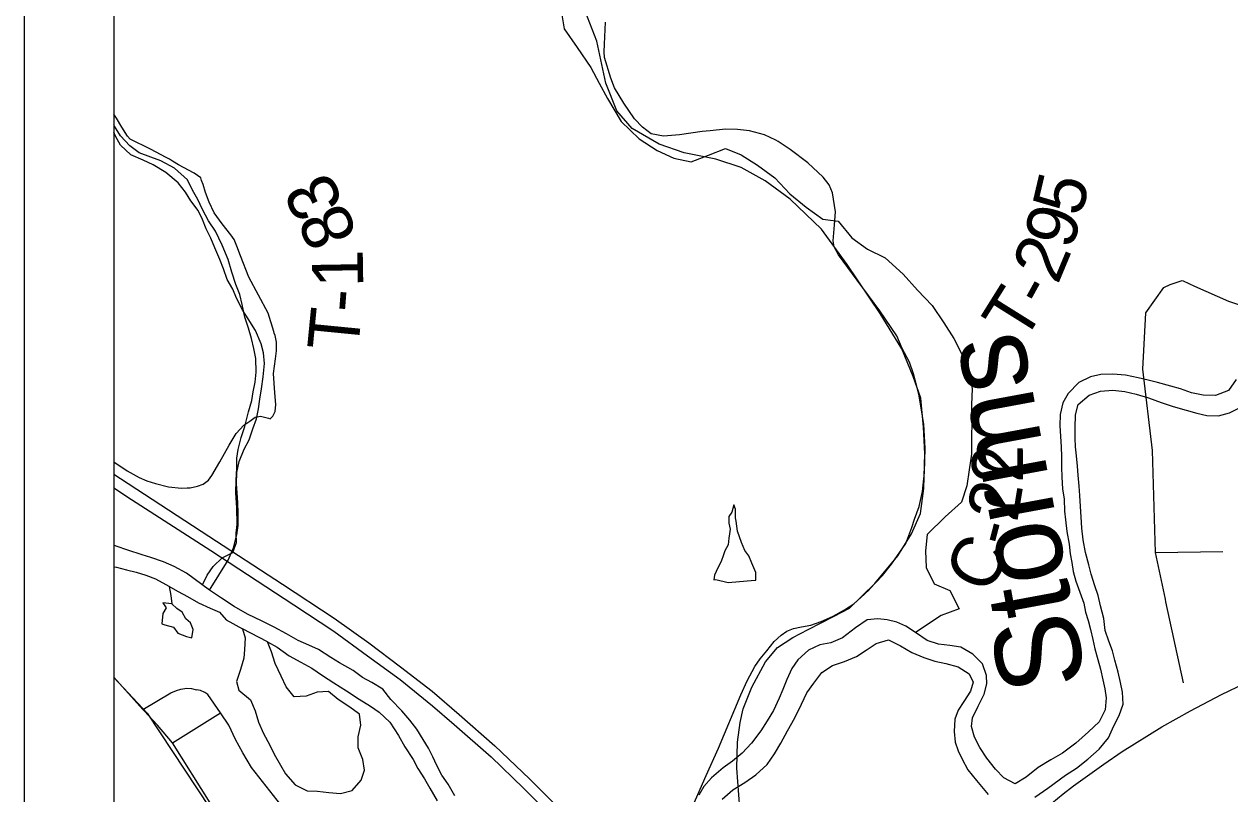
# Model space of a CAD drawing. Extents: x 0 to 34, y 0 to 22.
# Drawn here: x 2 to 3.344, y 16.541 to 17.398 of the extents above; entities that cross this region are included whole.
import ezdxf

# ---------------------------------------------------------------- set-up
doc = ezdxf.new("R2010")
doc.units = 0
for name, color, linetype in [('GM_X_City_Street', 7, 'Continuous'), ('GM_X_County_Road', 7, 'Continuous'), ('GM_X_County_Road_Text', 7, 'Continuous'), ('GM_X_Major_River', 7, 'Continuous'), ('GM_X_Minor_Lake', 7, 'Continuous'), ('GM_X_Minor_River', 7, 'Continuous'), ('GM_X_Minor_River_Text', 7, 'Continuous'), ('GM_X_Rail_Line', 7, 'Continuous'), ('GM_X_State_Route', 7, 'Continuous'), ('GM_X_Township_Road', 7, 'Continuous'), ('GM_X_Township_Road_Text', 7, 'Continuous'), ('GM_X_US_Route', 7, 'Continuous'), ('SH_Data', 7, 'Continuous')]:
    doc.layers.add(name, color=color, linetype=linetype)

msp = doc.modelspace()

# ---------------------------------------------------------------- linework, layer by layer
at = {"layer": 'GM_X_City_Street'}
msp.add_line((2.1653, 16.5976), (2.219, 16.6309), dxfattribs=at)
for points in [[(2.3346, 16.3321), (2.3012, 16.3848), (2.2686, 16.4364), (2.236, 16.4885), (2.2075, 16.5308), (2.1653, 16.5976), (2.1485, 16.6172), (2.1338, 16.6332), (2.1324, 16.6347), (2.1, 16.6709)], [(2.1324, 16.6347), (2.1637, 16.6534), (2.1697, 16.656), (2.1747, 16.6575), (2.1812, 16.6586), (2.1866, 16.6582), (2.1921, 16.6568)], [(2.2903, 16.5234), (2.2536, 16.57), (2.2437, 16.5863), (2.2355, 16.6011), (2.2283, 16.6172), (2.219, 16.6309), (2.2047, 16.6513), (2.2014, 16.6535), (2.1967, 16.6557), (2.1921, 16.6568)]]:
    msp.add_lwpolyline(points, dxfattribs=at)
at = {"layer": 'GM_X_County_Road'}
for points in [[(2.8377, 17.269), (2.8253, 17.2752), (2.8084, 17.2794), (2.7953, 17.2811), (2.7819, 17.2814), (2.7647, 17.2797), (2.7557, 17.2787), (2.7306, 17.2752), (2.7127, 17.2735), (2.699, 17.2763), (2.6893, 17.2835), (2.6804, 17.2931), (2.6683, 17.3104), (2.6579, 17.3275), (2.654, 17.3383), (2.6469, 17.3614), (2.6466, 17.3675), (2.6469, 17.3761), (2.6481, 17.4006)], [(2.9926, 16.8469), (2.9975, 16.8609), (3.0013, 16.8778), (3.0034, 16.8987), (3.0042, 16.9259), (3.0027, 16.9525), (2.9972, 16.9862), (2.9915, 17.0086), (2.9867, 17.0217), (2.9787, 17.0371), (2.9728, 17.0512), (2.9538, 17.0788), (2.9287, 17.1132), (2.9077, 17.1414), (2.9029, 17.1502), (2.9018, 17.1568), (2.9032, 17.1749), (2.9044, 17.1892), (2.901, 17.2105), (2.8972, 17.2195), (2.8907, 17.2281), (2.8734, 17.2439), (2.8538, 17.2587), (2.8404, 17.2677), (2.8377, 17.269)], [(2.9428, 16.7692), (2.9569, 16.7841), (2.9667, 16.7965), (2.9829, 16.8198), (2.9893, 16.8376), (2.9926, 16.8469)], [(2.7603, 16.5611), (2.7738, 16.5915), (2.799, 16.6512), (2.8061, 16.6668), (2.8146, 16.6825), (2.8204, 16.691), (2.8277, 16.7002), (2.8362, 16.7106), (2.8439, 16.7174), (2.85, 16.7219), (2.8576, 16.725), (2.8666, 16.7267), (2.8768, 16.7288), (2.8884, 16.7326), (2.9017, 16.7387), (2.9145, 16.7459), (2.9247, 16.7524), (2.9366, 16.7633), (2.9422, 16.7685), (2.9428, 16.7692)], [(2.7361, 16.508), (2.7457, 16.5281), (2.7603, 16.5611)]]:
    msp.add_lwpolyline(points, dxfattribs=at)
at = {"layer": 'GM_X_Major_River'}
msp.add_line((2.2714, 16.7102), (2.2435, 16.7247), dxfattribs=at)
for points in [[(3.3511, 17.0025), (3.3424, 16.9903), (3.328, 16.9846), (3.3141, 16.985), (3.3012, 16.9877), (3.2891, 16.9922), (3.2781, 16.9952), (3.2634, 16.999), (3.2528, 17.0017), (3.2419, 17.0043), (3.2275, 17.0074), (3.2135, 17.0085), (3.2003, 17.0081), (3.1886, 17.0055), (3.1757, 16.999), (3.1636, 16.9869), (3.1579, 16.9766), (3.1549, 16.9633), (3.1545, 16.9508), (3.156, 16.9273), (3.1564, 16.9167), (3.1564, 16.9049), (3.1568, 16.8935), (3.1575, 16.8806), (3.1594, 16.8692), (3.1598, 16.8556), (3.1609, 16.8461), (3.1624, 16.8332), (3.1647, 16.8188), (3.1658, 16.8082), (3.1677, 16.7987), (3.1692, 16.7884), (3.1723, 16.7778), (3.1768, 16.7653), (3.181, 16.7532), (3.1832, 16.7433), (3.1859, 16.7338), (3.1885, 16.7239), (3.1912, 16.7126), (3.1934, 16.7023), (3.1968, 16.6906), (3.1998, 16.6796), (3.2025, 16.6678), (3.2044, 16.6576), (3.2059, 16.6477)], [(3.2085, 16.6033), (3.2146, 16.6166), (3.2206, 16.628), (3.2252, 16.6405), (3.2244, 16.6542), (3.2221, 16.6648), (3.2195, 16.6762), (3.2157, 16.6898), (3.2131, 16.7001), (3.2089, 16.7107), (3.2051, 16.7228), (3.2033, 16.7361), (3.1999, 16.7501), (3.1972, 16.7619), (3.1934, 16.7725), (3.1893, 16.7854), (3.1866, 16.796), (3.1829, 16.8097), (3.1806, 16.8237), (3.1791, 16.8366), (3.1783, 16.8495), (3.1776, 16.8609), (3.1768, 16.873), (3.1761, 16.8837), (3.1749, 16.8958), (3.1742, 16.9057), (3.173, 16.9174), (3.1719, 16.9273), (3.1715, 16.9372), (3.1715, 16.9485), (3.1719, 16.963), (3.1749, 16.9747), (3.187, 16.985), (3.1999, 16.9895), (3.2135, 16.9907), (3.2267, 16.9892), (3.2396, 16.9861), (3.2532, 16.982), (3.2672, 16.977), (3.2808, 16.9725), (3.2952, 16.9683), (3.3073, 16.9649), (3.3182, 16.9623), (3.3314, 16.9619), (3.3435, 16.9653), (3.356, 16.9718)], [(2.3417, 16.6928), (2.3281, 16.7015), (2.3175, 16.7064), (2.3054, 16.7117), (2.2926, 16.7189), (2.2786, 16.7265), (2.2654, 16.733), (2.2491, 16.7409), (2.234, 16.7496), (2.22, 16.7587), (2.2068, 16.7678), (2.1811, 16.7868), (2.1671, 16.794), (2.1554, 16.7993), (2.1414, 16.8042), (2.1316, 16.8072), (2.1157, 16.8122), (2.1025, 16.8167), (2.1, 16.8178)], [(2.1, 16.7938), (2.1028, 16.7932), (2.1142, 16.7905), (2.1248, 16.7879), (2.1357, 16.7845), (2.1463, 16.7803), (2.158, 16.7739), (2.1716, 16.7663), (2.1822, 16.7606), (2.1943, 16.7534), (2.2072, 16.7477), (2.2177, 16.7432), (2.2252, 16.7346), (2.2435, 16.7247)], [(3.2059, 16.6477), (3.2048, 16.6344), (3.1983, 16.6211), (3.1862, 16.6098), (3.1722, 16.5972), (3.1575, 16.5862), (3.1443, 16.5786), (3.1303, 16.5699), (3.117, 16.5593), (3.1046, 16.5517), (3.0921, 16.5585), (3.0826, 16.5684), (3.0732, 16.5805), (3.0653, 16.5923), (3.0592, 16.604), (3.0558, 16.6158), (3.0569, 16.6256), (3.0634, 16.6385), (3.0702, 16.6518), (3.0732, 16.6632), (3.0728, 16.6727), (3.0683, 16.6856), (3.0573, 16.6962), (3.0441, 16.7042), (3.032, 16.706), (3.0192, 16.7076), (3.0067, 16.7117), (2.9935, 16.7204), (2.9829, 16.7276), (2.9727, 16.7322), (2.9621, 16.7348), (2.9515, 16.7356), (2.9398, 16.7348), (2.9265, 16.7257), (2.9122, 16.7147), (2.8993, 16.709), (2.8868, 16.7067), (2.8744, 16.701), (2.8623, 16.69), (2.8558, 16.6805), (2.8502, 16.668), (2.8456, 16.657), (2.8415, 16.6472), (2.8354, 16.6335), (2.8282, 16.6221), (2.8211, 16.6111), (2.8108, 16.5971), (2.8003, 16.5861), (2.7897, 16.5773), (2.7791, 16.5697), (2.7662, 16.5587), (2.7575, 16.5489), (2.7522, 16.5394)], [(2.2435, 16.7247), (2.2465, 16.7144), (2.2457, 16.7015), (2.2449, 16.692), (2.2412, 16.6791), (2.2366, 16.6658), (2.2393, 16.6563), (2.2525, 16.6453), (2.2574, 16.6332), (2.2612, 16.6207), (2.2669, 16.6081), (2.2737, 16.5949), (2.2786, 16.585), (2.2858, 16.5725), (2.2914, 16.563), (2.302, 16.5509), (2.3156, 16.5441), (2.327, 16.5437), (2.3398, 16.5422), (2.3527, 16.5411), (2.3655, 16.5445), (2.3757, 16.5559), (2.3795, 16.5672), (2.3776, 16.579), (2.3723, 16.5919), (2.3723, 16.6044), (2.3754, 16.6173), (2.3738, 16.6295), (2.3621, 16.6382), (2.35, 16.6457), (2.3394, 16.6548), (2.3266, 16.6541), (2.3145, 16.6495), (2.3009, 16.6488), (2.2922, 16.6598), (2.2865, 16.6719), (2.2797, 16.6859), (2.2756, 16.6988), (2.2714, 16.7102)], [(2.2714, 16.7102), (2.282, 16.7041)], [(2.7779, 16.5348), (2.79, 16.5451), (2.8033, 16.5534), (2.8157, 16.5618), (2.8282, 16.5736), (2.8365, 16.5853), (2.8434, 16.5971), (2.8509, 16.6111), (2.8589, 16.6255), (2.8664, 16.6407), (2.8725, 16.6532), (2.8804, 16.6642), (2.8891, 16.676), (2.9012, 16.6836), (2.9144, 16.6882), (2.9277, 16.6939), (2.9386, 16.7007), (2.9496, 16.7083), (2.9636, 16.7125), (2.9768, 16.7056), (2.9893, 16.6981), (3.0029, 16.6928), (3.015, 16.6886), (3.0275, 16.6859), (3.0411, 16.6821), (3.0535, 16.6746), (3.0577, 16.6651), (3.0547, 16.6552), (3.0475, 16.6435), (3.0411, 16.634), (3.0373, 16.6241), (3.0365, 16.6101), (3.0377, 16.5983), (3.0411, 16.5888), (3.0456, 16.5793), (3.052, 16.5676), (3.0615, 16.5555), (3.0747, 16.5399)], [(2.282, 16.7041), (2.2956, 16.6947), (2.3085, 16.6875), (2.3206, 16.6806), (2.3326, 16.6727), (2.3451, 16.6643), (2.3595, 16.6556), (2.3735, 16.6461), (2.3859, 16.6386), (2.3958, 16.6317), (2.4075, 16.6207), (2.4173, 16.6056), (2.4245, 16.5931), (2.4336, 16.579), (2.4389, 16.5688), (2.4464, 16.5574), (2.4521, 16.5472), (2.4604, 16.5331)], [(2.4801, 16.5385), (2.4725, 16.5514), (2.4657, 16.5616), (2.46, 16.5722), (2.4555, 16.5821), (2.4506, 16.5916), (2.4449, 16.6014), (2.4377, 16.6128), (2.4298, 16.623), (2.4211, 16.6333), (2.4086, 16.6458), (2.3999, 16.6572), (2.3875, 16.6647), (2.3773, 16.6704), (2.3667, 16.678), (2.3516, 16.6867), (2.3417, 16.6928)], [(3.1265, 16.5369), (3.1412, 16.5471), (3.1609, 16.5616), (3.173, 16.5695), (3.1858, 16.5794), (3.1983, 16.5904), (3.2085, 16.6033)]]:
    msp.add_lwpolyline(points, dxfattribs=at)
at = {"layer": 'GM_X_Minor_Lake'}
for points in [[(2.791, 16.8627), (2.7887, 16.8547), (2.7856, 16.8498), (2.7856, 16.8422), (2.7871, 16.8358), (2.7863, 16.8305), (2.7856, 16.8255), (2.7848, 16.8183), (2.781, 16.8115), (2.7795, 16.807), (2.7768, 16.7998), (2.7741, 16.7941), (2.7715, 16.7884), (2.7696, 16.7843), (2.7688, 16.7793), (2.7711, 16.7797)], [(2.7711, 16.7797), (2.7847, 16.7762), (2.7972, 16.7773), (2.8104, 16.7784), (2.8157, 16.7788), (2.8154, 16.7875), (2.8112, 16.7978), (2.8079, 16.8061), (2.8033, 16.8118), (2.7996, 16.8209), (2.7951, 16.8335), (2.7936, 16.8445), (2.7928, 16.8483), (2.7928, 16.8578), (2.791, 16.8627)], [(2.1647, 16.7523), (2.1545, 16.7535), (2.1582, 16.7481), (2.1548, 16.7417), (2.1536, 16.7303), (2.157, 16.7292), (2.1665, 16.7265), (2.1714, 16.7196), (2.1763, 16.7181), (2.1809, 16.7162), (2.1869, 16.7146)], [(2.1869, 16.7146), (2.1884, 16.7237), (2.1854, 16.7313), (2.1801, 16.7359), (2.176, 16.7431), (2.1703, 16.7473), (2.1647, 16.7523)]]:
    msp.add_lwpolyline(points, dxfattribs=at)
at = {"layer": 'GM_X_Minor_River'}
for points in [[(2.5991, 17.411), (2.6021, 17.3931), (2.6165, 17.3725), (2.6316, 17.35), (2.641, 17.3325), (2.6504, 17.3154), (2.6655, 17.2899), (2.6855, 17.2705), (2.7056, 17.2575), (2.7241, 17.2491), (2.7434, 17.2449), (2.7627, 17.2525), (2.7817, 17.2597), (2.7991, 17.2529), (2.8176, 17.2414), (2.8368, 17.227), (2.8535, 17.2094), (2.8716, 17.1946), (2.8901, 17.1812), (2.9075, 17.179), (2.9226, 17.1603), (2.94, 17.1477), (2.9597, 17.1382), (2.9797, 17.1199), (2.9959, 17.102), (3.0122, 17.0849), (3.025, 17.0655), (3.0363, 17.0483), (3.0454, 17.0301), (3.054, 17.0099), (3.0566, 16.992), (3.0558, 16.9745), (3.0562, 16.9551), (3.0558, 16.9376), (3.0561, 16.9193), (3.0534, 16.9018), (3.0507, 16.884), (3.045, 16.8657), (3.0268, 16.8494), (3.0067, 16.8296), (3.0047, 16.8114), (3.0055, 16.7931), (3.0145, 16.7748), (3.0319, 16.7672), (3.0421, 16.747), (3.022, 16.7395), (2.9935, 16.7204)], [(2.1987, 16.7738), (2.2041, 16.7844), (2.2106, 16.7942), (2.2208, 16.8037), (2.2326, 16.8097), (2.2368, 16.8207), (2.2364, 16.8313), (2.2376, 16.8408), (2.2372, 16.8594), (2.2358, 16.8761), (2.2362, 16.8901), (2.237, 16.9034), (2.237, 16.9148), (2.2385, 16.9246), (2.242, 16.9379), (2.2462, 16.95), (2.25, 16.9663), (2.2538, 16.9792), (2.2554, 16.9887), (2.2576, 16.9993), (2.2588, 17.0107), (2.2581, 17.0259), (2.2562, 17.0369), (2.2536, 17.0483), (2.2502, 17.0597), (2.2461, 17.0718), (2.2431, 17.0859), (2.2405, 17.0973), (2.236, 17.1083), (2.2315, 17.122), (2.2273, 17.136), (2.2209, 17.152), (2.2134, 17.1676), (2.2055, 17.1794), (2.1987, 17.1919), (2.1938, 17.2029), (2.1878, 17.2136), (2.1822, 17.225), (2.1678, 17.2379), (2.1523, 17.246), (2.1413, 17.2502), (2.1281, 17.2552), (2.1179, 17.2628), (2.1073, 17.2738), (2.1009, 17.2848), (2.1, 17.2864)], [(2.2068, 16.7678), (2.2276, 16.8012), (2.2333, 16.8149), (2.237, 16.8293), (2.2386, 16.8399), (2.2386, 16.8536), (2.2382, 16.865), (2.2374, 16.8763), (2.2367, 16.8862), (2.2371, 16.8987), (2.2397, 16.9109), (2.2454, 16.9249), (2.2507, 16.9352), (2.2548, 16.9473), (2.259, 16.9587), (2.2613, 16.9697), (2.2628, 16.9807), (2.2647, 16.9921), (2.2666, 17.0054), (2.2681, 17.0202), (2.2669, 17.0323), (2.2643, 17.0422), (2.2579, 17.057), (2.2499, 17.0699), (2.2439, 17.0793), (2.2367, 17.093), (2.2326, 17.1032), (2.2265, 17.1139), (2.2224, 17.1256), (2.2182, 17.1362), (2.2125, 17.1491), (2.208, 17.1598), (2.2031, 17.1704), (2.1989, 17.1806), (2.194, 17.1909), (2.1857, 17.2015), (2.1797, 17.2113), (2.1717, 17.2216), (2.1581, 17.233), (2.1438, 17.2417), (2.1328, 17.247), (2.1188, 17.2527), (2.1075, 17.2637), (2.1018, 17.2735), (2.1, 17.2782)], [(2.1617, 16.7718), (2.1636, 16.7618), (2.1647, 16.7523), (2.1643, 16.753)]]:
    msp.add_lwpolyline(points, dxfattribs=at)
at = {"layer": 'GM_X_Rail_Line'}
for points in [[(2.8011, 16.4801), (2.7943, 16.5694), (2.7951, 16.5984), (2.7983, 16.6201), (2.8015, 16.6354), (2.8112, 16.6595), (2.8265, 16.6877), (2.8398, 16.7037), (2.857, 16.7149), (2.8741, 16.724), (2.9028, 16.7386), (2.92, 16.7478), (2.9481, 16.7751), (2.9737, 16.806), (2.9891, 16.8305), (2.9992, 16.8531), (3.003, 16.8811), (3.004, 16.92), (3.0023, 16.9492), (2.9995, 16.9815), (2.991, 17.0058), (2.9782, 17.0368), (2.954, 17.0761), (2.9175, 17.1307), (2.8886, 17.1698), (2.8539, 17.2033), (2.8261, 17.2238), (2.7994, 17.2388), (2.7709, 17.2479), (2.7356, 17.255), (2.7077, 17.2646), (2.6776, 17.2821), (2.6606, 17.3019), (2.6483, 17.3328), (2.6383, 17.3794), (2.6229, 17.4196)], [(2.1, 16.6705), (2.1371, 16.6305), (2.4442, 16.1664)]]:
    msp.add_lwpolyline(points, dxfattribs=at)
at = {"layer": 'GM_X_State_Route'}
msp.add_lwpolyline([(3.102, 16.494), (3.1088, 16.5002), (3.1391, 16.5253), (3.158, 16.5407), (3.1695, 16.5496), (3.2033, 16.5739), (3.224, 16.5878), (3.2682, 16.6153), (3.2999, 16.6333), (3.3345, 16.6514), (3.3611, 16.6641), (3.3624, 16.6646), (3.3885, 16.6767), (3.4167, 16.6883), (3.4364, 16.6961), (3.4525, 16.702), (3.4601, 16.7051), (3.4709, 16.7083), (3.4917, 16.7154), (3.5156, 16.7225), (3.5371, 16.7279)], dxfattribs=at)
at = {"layer": 'GM_X_Township_Road'}
for p, q in [((2.2788, 17.0542), (2.2782, 17.0561)), ((3.2609, 16.8095), (3.336, 16.8108))]:
    msp.add_line(p, q, dxfattribs=at)
for points in [[(3.2918, 17.1124), (3.3044, 17.1065), (3.3425, 17.0897), (3.3603, 17.0839), (3.3743, 17.0863), (3.3801, 17.0941), (3.3895, 17.1174), (3.3998, 17.1342), (3.4089, 17.148), (3.4206, 17.1579), (3.4373, 17.1726), (3.4472, 17.1863), (3.4553, 17.2051), (3.4545, 17.2306), (3.4393, 17.2664), (3.4369, 17.2752), (3.4364, 17.2854), (3.4333, 17.2973), (3.4326, 17.3106), (3.4347, 17.3315), (3.441, 17.3544), (3.4498, 17.3701)], [(2.1584, 17.2497), (2.1408, 17.2591), (2.1183, 17.2703), (2.1152, 17.2736), (2.1088, 17.2836), (2.103, 17.2938), (2.1, 17.2982)], [(2.1653, 17.2457), (2.1619, 17.2478), (2.1584, 17.2497)], [(2.2782, 17.0561), (2.2719, 17.0764), (2.2503, 17.1164), (2.2412, 17.1402), (2.2372, 17.1509), (2.234, 17.1586), (2.2304, 17.1638), (2.2207, 17.176), (2.212, 17.1881), (2.2064, 17.1999), (2.202, 17.211), (2.1994, 17.2197), (2.1979, 17.2242), (2.1969, 17.2271), (2.1895, 17.2325), (2.1721, 17.2415), (2.1653, 17.2457)], [(3.2721, 16.7578), (3.2609, 16.8095), (3.2576, 16.9234), (3.247, 17.0138), (3.2503, 17.0767), (3.2705, 17.105), (3.2774, 17.1082), (3.2909, 17.1128), (3.2918, 17.1124)], [(2.2725, 16.9592), (2.2744, 16.9586), (2.2771, 16.9615), (2.2799, 16.9667), (2.2806, 16.9747), (2.2793, 16.9875), (2.2778, 17.009), (2.2802, 17.0255), (2.2813, 17.0343), (2.2812, 17.0442), (2.2797, 17.0513), (2.2788, 17.0542)], [(2.1818, 16.8816), (2.1849, 16.8817), (2.1933, 16.8837), (2.1995, 16.8859), (2.2055, 16.8904), (2.2092, 16.8953), (2.2181, 16.9106), (2.2285, 16.9292), (2.2364, 16.9421), (2.2448, 16.9514), (2.2517, 16.9561), (2.2574, 16.9606), (2.2636, 16.9616), (2.2725, 16.9592)], [(2.1, 16.9106), (2.115, 16.9008), (2.1283, 16.8933), (2.1367, 16.8896), (2.1466, 16.8864), (2.1609, 16.883), (2.1755, 16.8815), (2.1818, 16.8816)], [(3.2922, 16.6646), (3.2727, 16.7547), (3.2721, 16.7578)]]:
    msp.add_lwpolyline(points, dxfattribs=at)
at = {"layer": 'GM_X_US_Route'}
for points in [[(2.1, 16.8968), (2.1074, 16.892), (2.2058, 16.828), (2.2879, 16.7742), (2.3455, 16.7364), (2.3844, 16.7089), (2.4196, 16.6824), (2.4547, 16.6553), (2.4851, 16.629), (2.5248, 16.5941), (2.5632, 16.5574), (2.6001, 16.5206)], [(2.1, 16.8819), (2.1197, 16.8689), (2.2082, 16.8119), (2.3007, 16.7515), (2.3453, 16.7219), (2.3829, 16.6947), (2.4191, 16.668), (2.4552, 16.6389), (2.4792, 16.6181), (2.5204, 16.5821), (2.5567, 16.5472), (2.5947, 16.5087), (2.6311, 16.4689), (2.663, 16.4325), (2.6859, 16.4074), (2.7306, 16.3565), (2.7678, 16.3138)]]:
    msp.add_lwpolyline(points, dxfattribs=at)
at = {"layer": 'SH_Data'}
for p, q in [((2, 21), (2, 14)), ((2.1, 20.9), (2.1, 14.1))]:
    msp.add_line(p, q, dxfattribs=at)

# ---------------------------------------------------------------- texts
at = {"layer": 'GM_X_County_Road_Text'}
for s, rotation, p in [('2', 90.3391, (3.1134, 16.8875)), ('2', 80.6034, (3.1068, 16.8425)), ('-', 75.2745, (3.0997, 16.8143)), ('C', 64.3047, (3.0754, 16.7611))]:
    msp.add_text(s, height=0.0568, rotation=rotation, dxfattribs=at).set_placement(p)
at = {"layer": 'GM_X_Minor_River_Text'}
msp.add_text('Storms', height=0.09472, rotation=100.4919, dxfattribs=at).set_placement((3.1844, 16.6646))
at = {"layer": 'GM_X_Township_Road_Text'}
for s, rotation, p in [('3', 116.3814, (2.3571, 17.1987)), ('5', 76.8256, (3.1784, 17.1828)), ('8', 113.5752, (2.3724, 17.1639)), ('9', 73.6777, (3.1677, 17.1459)), ('2', 67.3819, (3.152, 17.1072)), ('1', 90.9506, (2.3781, 17.1052)), ('T', 57.9383, (3.1135, 17.0417)), ('-', 61.0862, (3.1378, 17.0806)), ('-', 85.6704, (2.3762, 17.0762)), ('T', 84.4156, (2.372, 17.0325))]:
    msp.add_text(s, height=0.0568, rotation=rotation, dxfattribs=at).set_placement(p)

doc.saveas('drawing.dxf')
